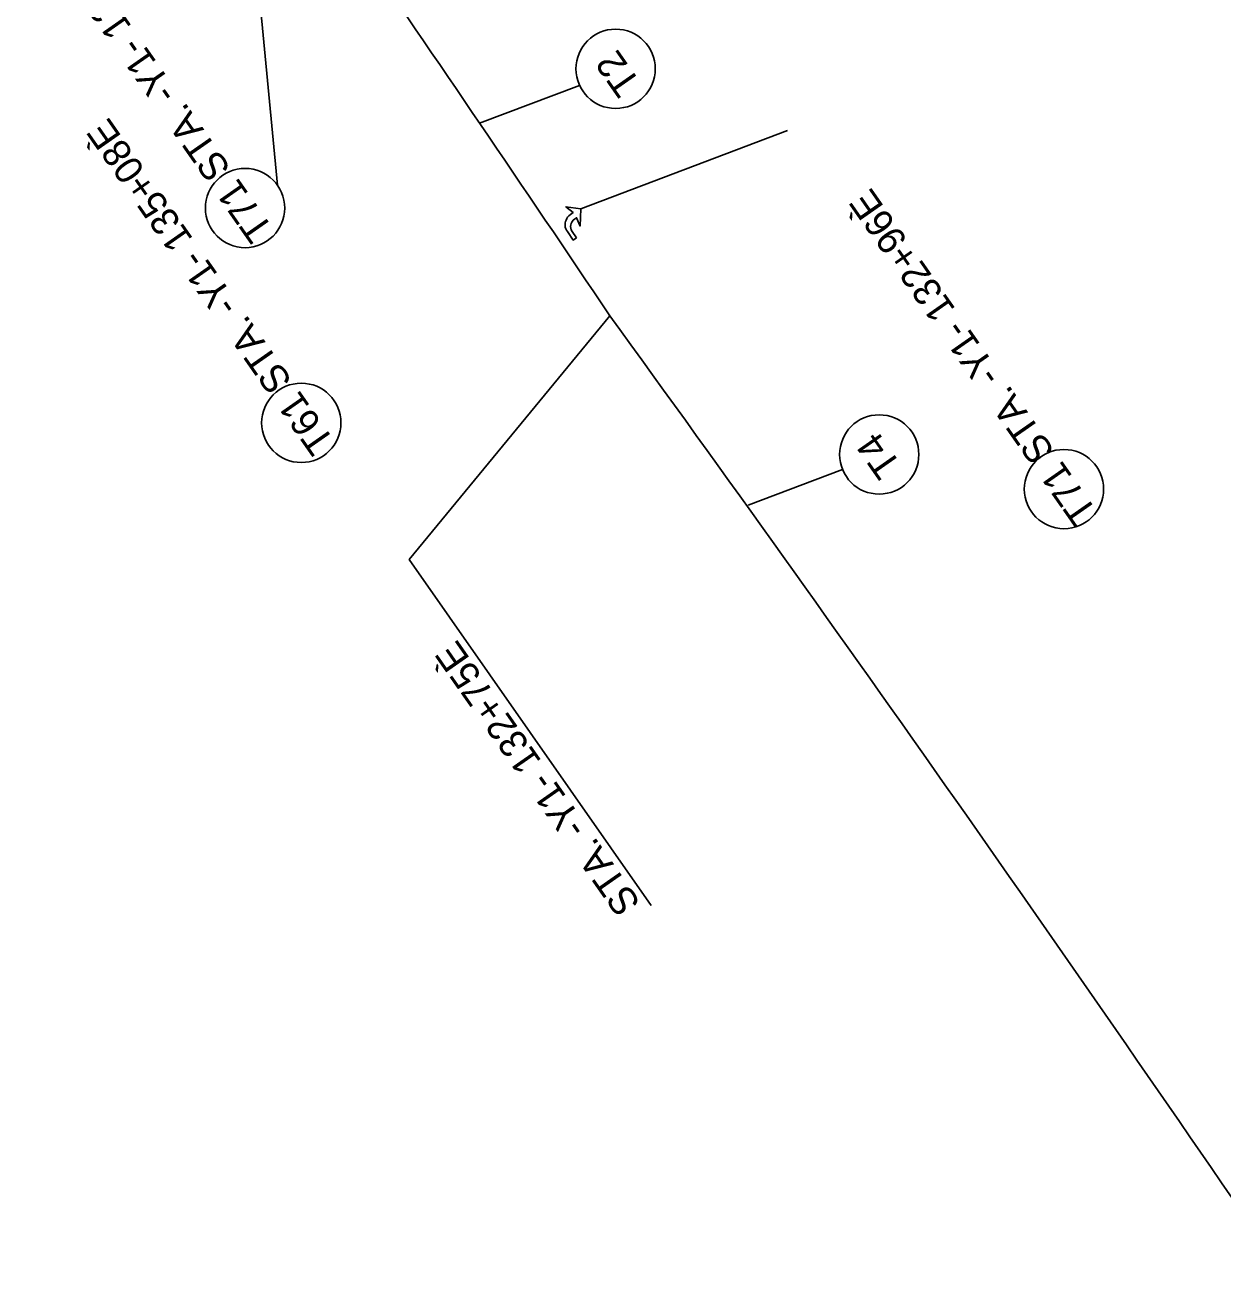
# Model space of a CAD drawing. Extents: x 1487421 to 1489048, y 497792 to 499463.
# Drawn here: x 1487797.2 to 1488099.3, y 497860.2 to 498179.4 of the extents above; entities that cross this region are included whole.
import ezdxf

# ---------------------------------------------------------------- set-up
doc = ezdxf.new("R2010")
doc.units = 0
for name, color, linetype in [('MARK RIGHT ONLY RIGHT SYMBOL CELL', 7, 'Continuous'), ('Prop Mkg 3ft Min Skp 9ft White', 7, 'Continuous'), ('Prop Mkg Solid White Edge Line', 7, 'Continuous'), ('Text', 7, 'Continuous')]:
    doc.layers.add(name, color=color, linetype=linetype)

msp = doc.modelspace()

# ---------------------------------------------------------------- linework, layer by layer
at = {"layer": 'MARK RIGHT ONLY RIGHT SYMBOL CELL'}
msp.add_lwpolyline([(1487936.29, 498125.8), (1487935.47, 498125.23), (1487934, 498127.36), (1487933.75, 498127.77), (1487933.6, 498128.1), (1487933.48, 498128.5), (1487933.43, 498128.87), (1487933.43, 498129.17), (1487933.48, 498129.6), (1487933.56, 498129.93), (1487933.67, 498130.29), (1487933.87, 498130.71), (1487934.05, 498130.99), (1487934.33, 498131.34), (1487934.77, 498131.73), (1487935.43, 498132.19), (1487933.61, 498133.66), (1487937.4, 498133.14), (1487937.19, 498128.75), (1487936.33, 498130.88), (1487935.78, 498130.51), (1487935.48, 498130.28), (1487935.25, 498130), (1487935.1, 498129.75), (1487934.93, 498129.38), (1487934.85, 498129.09), (1487934.81, 498128.67), (1487934.87, 498128.25), (1487934.97, 498127.86), (1487935.2, 498127.38)], close=True, dxfattribs=at)
at = {"layer": 'Prop Mkg 3ft Min Skp 9ft White'}
msp.add_arc((1479834.34, 492219.83), 10021.31, 34.252314, 35.973491, dxfattribs=at)
at = {"layer": 'Prop Mkg Solid White Edge Line'}
msp.add_arc((1479623.58, 492519.58), 10022.5, 33.876157, 35.209476, dxfattribs=at)
at = {"layer": 'Text'}
for p, q in [((1487860.86, 498139.07), (1487850.41, 498248.78)), ((1487937.08, 498164.27), (1487911.86, 498154.74)), ((1487989.55, 498152.84), (1487937.4, 498133.14)), ((1487894.11, 498044.68), (1487944.71, 498106.12)), ((1488003.43, 498067.33), (1487979.62, 498058.33)), ((1487894.11, 498044.68), (1487955.16, 497957.34))]:
    msp.add_line(p, q, dxfattribs=at)
for centre in [(1487946.17, 498168.44), (1487852.69, 498133.31), (1487866.87, 498079.13), (1488012.67, 498071.15), (1488059.28, 498062.41)]:
    msp.add_circle(centre, 10, dxfattribs=at)

# ---------------------------------------------------------------- texts
for s, rotation, p in [('T71 STA. -Y1- 134+46È', 124.9556, (1487860.02, 498127.9)), ('T2', 124.9556, (1487952.74, 498164.72)), ('T61 STA. -Y1- 135+08È', 124.9556, (1487875.5, 498074.33)), ('T71 STA. -Y1- 132+96È', 124.9556, (1488067.86, 498056.61)), ('T4', 124.9556, (1488018.48, 498068.31)), ('STA. -Y1- 132+75È', 124.9554, (1487952.67, 497957.94))]:
    msp.add_text(s, height=7, rotation=rotation, dxfattribs=at).set_placement(p)

doc.saveas('drawing.dxf')
